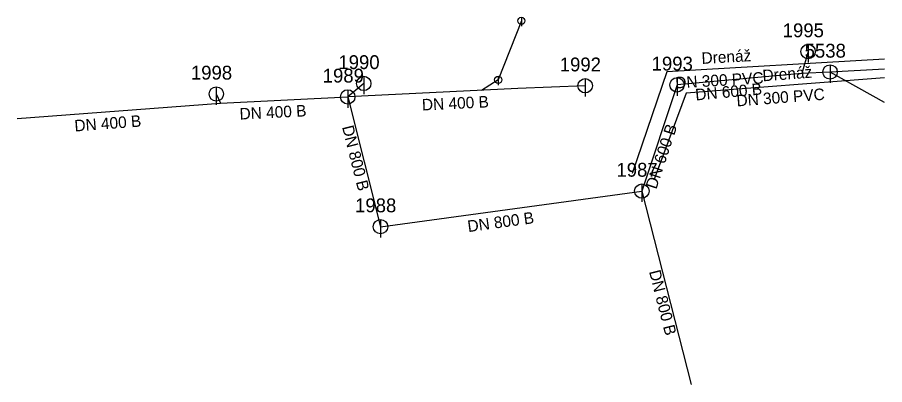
# Model space of a CAD drawing. Extents: x -466380 to -466260, y -1119147 to -1119096.
import ezdxf

# ---------------------------------------------------------------- set-up
doc = ezdxf.new("R2010")
doc.units = 0
for name, color, linetype in [('_pripojka_kanal_jednotna_priblizne_', 7, 'Continuous'), ('_stoka_destova_smvak_prevzato_z_dokumentace_', 7, 'Continuous'), ('_stoka_jednotna_smvak_prevzato_z_dokumentace_', 7, 'Continuous'), ('Default', 7, 'Continuous'), ('MoLevel 119', 7, 'Continuous'), ('MoLevel 120', 7, 'Continuous'), ('MoLevel 57', 7, 'Continuous'), ('MoLevel 68', 7, 'Continuous'), ('MoLevel 74', 7, 'Continuous'), ('MoLevel 75', 7, 'Continuous')]:
    doc.layers.add(name, color=color, linetype=linetype)

# ---------------------------------------------------------------- blocks, each defined once
blk = doc.blocks.new('_sachta_kanal_prip_')
at = {"layer": 'Default'}
blk.add_line((0, 0.00005), (0, -0.000075), dxfattribs=at)
blk.add_circle((0, 0), 0.00005, dxfattribs=at)
blk = doc.blocks.new('_sachta_kanal_prevzato_z_dokumentace_')
at = {"layer": 'Default'}
blk.add_line((0, 0.00005), (0, -0.000075), dxfattribs=at)
blk.add_circle((0, 0), 0.00005, dxfattribs=at)

msp = doc.modelspace()

# ---------------------------------------------------------------- linework, layer by layer
at = {"layer": '_pripojka_kanal_jednotna_priblizne_'}
for p, q in [((-466310.23, -1119096.22), (-466313.44, -1119104.42)), ((-466313.44, -1119104.42), (-466315.77, -1119105.88))]:
    msp.add_line(p, q, dxfattribs=at)
at = {"layer": '_stoka_destova_smvak_prevzato_z_dokumentace_'}
for points in [[(-466259.73, -1119101.55), (-466290.02, -1119103.29), (-466294.82, -1119117.44)], [(-466259.73, -1119104.14), (-466287.3, -1119106.25), (-466291.81, -1119118.39)]]:
    msp.add_lwpolyline(points, dxfattribs=at)
at = {"layer": '_stoka_jednotna_smvak_prevzato_z_dokumentace_'}
for p, q in [((-466270.37, -1119100.49), (-466271.26, -1119103.54)), ((-466271.26, -1119103.54), (-466288.59, -1119105.12)), ((-466267.32, -1119103.33), (-466271.26, -1119103.54)), ((-466259.73, -1119102.92), (-466267.32, -1119103.33)), ((-466259.73, -1119107.57), (-466267.32, -1119103.33)), ((-466332.13, -1119104.92), (-466334.36, -1119106.79)), ((-466288.59, -1119105.12), (-466293.48, -1119119.89)), ((-466352.63, -1119106.38), (-466352.07, -1119107.67)), ((-466352.07, -1119107.67), (-466334.36, -1119106.79)), ((-466334.36, -1119106.79), (-466329.81, -1119124.84)), ((-466380.29, -1119109.81), (-466352.07, -1119107.67)), ((-466329.81, -1119124.84), (-466293.48, -1119119.89)), ((-466293.48, -1119119.89), (-466286.63, -1119146.81))]:
    msp.add_line(p, q, dxfattribs=at)
msp.add_lwpolyline([(-466301.36, -1119105.24), (-466310.72, -1119105.64), (-466334.36, -1119106.79)], dxfattribs=at)

# ---------------------------------------------------------------- block references
at = {"layer": 'MoLevel 119', "xscale": 20000, "yscale": 20000}
for p in [(-466270.37, -1119100.49), (-466267.32, -1119103.33), (-466332.13, -1119104.92), (-466301.36, -1119105.24), (-466288.59, -1119105.12), (-466352.63, -1119106.38), (-466334.36, -1119106.79), (-466293.48, -1119119.89), (-466329.81, -1119124.84)]:
    msp.add_blockref('_sachta_kanal_prevzato_z_dokumentace_', p, dxfattribs=at)
at = {"layer": 'MoLevel 57', "xscale": 10000, "yscale": 10000}
for p in [(-466310.23, -1119096.22), (-466313.44, -1119104.42)]:
    msp.add_blockref('_sachta_kanal_prip_', p, dxfattribs=at)

# ---------------------------------------------------------------- texts
at = {"layer": 'MoLevel 120'}
for s, p in [('1995', (-466273.9, -1119098.49)), ('5538', (-466270.85, -1119101.33)), ('1990', (-466335.66, -1119102.92)), ('1992', (-466304.89, -1119103.24)), ('1993', (-466292.12, -1119103.12)), ('1998', (-466356.16, -1119104.38)), ('1989', (-466337.84, -1119104.79)), ('1987', (-466297.01, -1119117.89)), ('1988', (-466333.34, -1119122.84))]:
    msp.add_text(s, height=1.926, dxfattribs=at).set_placement(p)
at = {"layer": 'MoLevel 68'}
for s, rotation, p in [('DN 600 B', 5.1909, (-466285.98, -1119107.29)), ('DN 400 B', 2.7877, (-466324.01, -1119108.69)), ('DN 400 B', 2.8568, (-466349.36, -1119109.95)), ('DN 400 B', 4.3227, (-466372.29, -1119111.61)), ('DN 800 B', 284.131, (-466335.16, -1119110.97)), ('DN 600 B', 71.6978, (-466291.47, -1119119.72)), ('DN 800 B', 7.764, (-466317.6, -1119125.6)), ('DN 800 B', 284.2802, (-466292.49, -1119131.08))]:
    msp.add_text(s, height=1.605, rotation=rotation, dxfattribs=at).set_placement(p)
at = {"layer": 'MoLevel 74'}
for rotation, p in [(3.2742, (-466288.79, -1119105.62)), (4.3773, (-466280.26, -1119108.12))]:
    msp.add_text('DN 300 PVC', height=1.605, rotation=rotation, dxfattribs=at).set_placement(p)
at = {"layer": 'MoLevel 75'}
for rotation, p in [(3.2742, (-466285.14, -1119102.21)), (4.3773, (-466276.65, -1119104.63))]:
    msp.add_text('Drenáž', height=1.605, rotation=rotation, dxfattribs=at).set_placement(p)

doc.saveas('drawing.dxf')
